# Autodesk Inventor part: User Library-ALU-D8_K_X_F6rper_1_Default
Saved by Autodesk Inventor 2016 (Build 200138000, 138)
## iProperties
Created: 2012-01
Part Number: User Library-ALU-D8_K_X_F6rper_1_Default
Document SubType Name: Modeling
Designer: Trevor
Density: 1 g/cm^3
Material: Generic
Appearance: 202,202,202
Author: Trevor
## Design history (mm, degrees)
feature "Base1"
node "Imported1"
